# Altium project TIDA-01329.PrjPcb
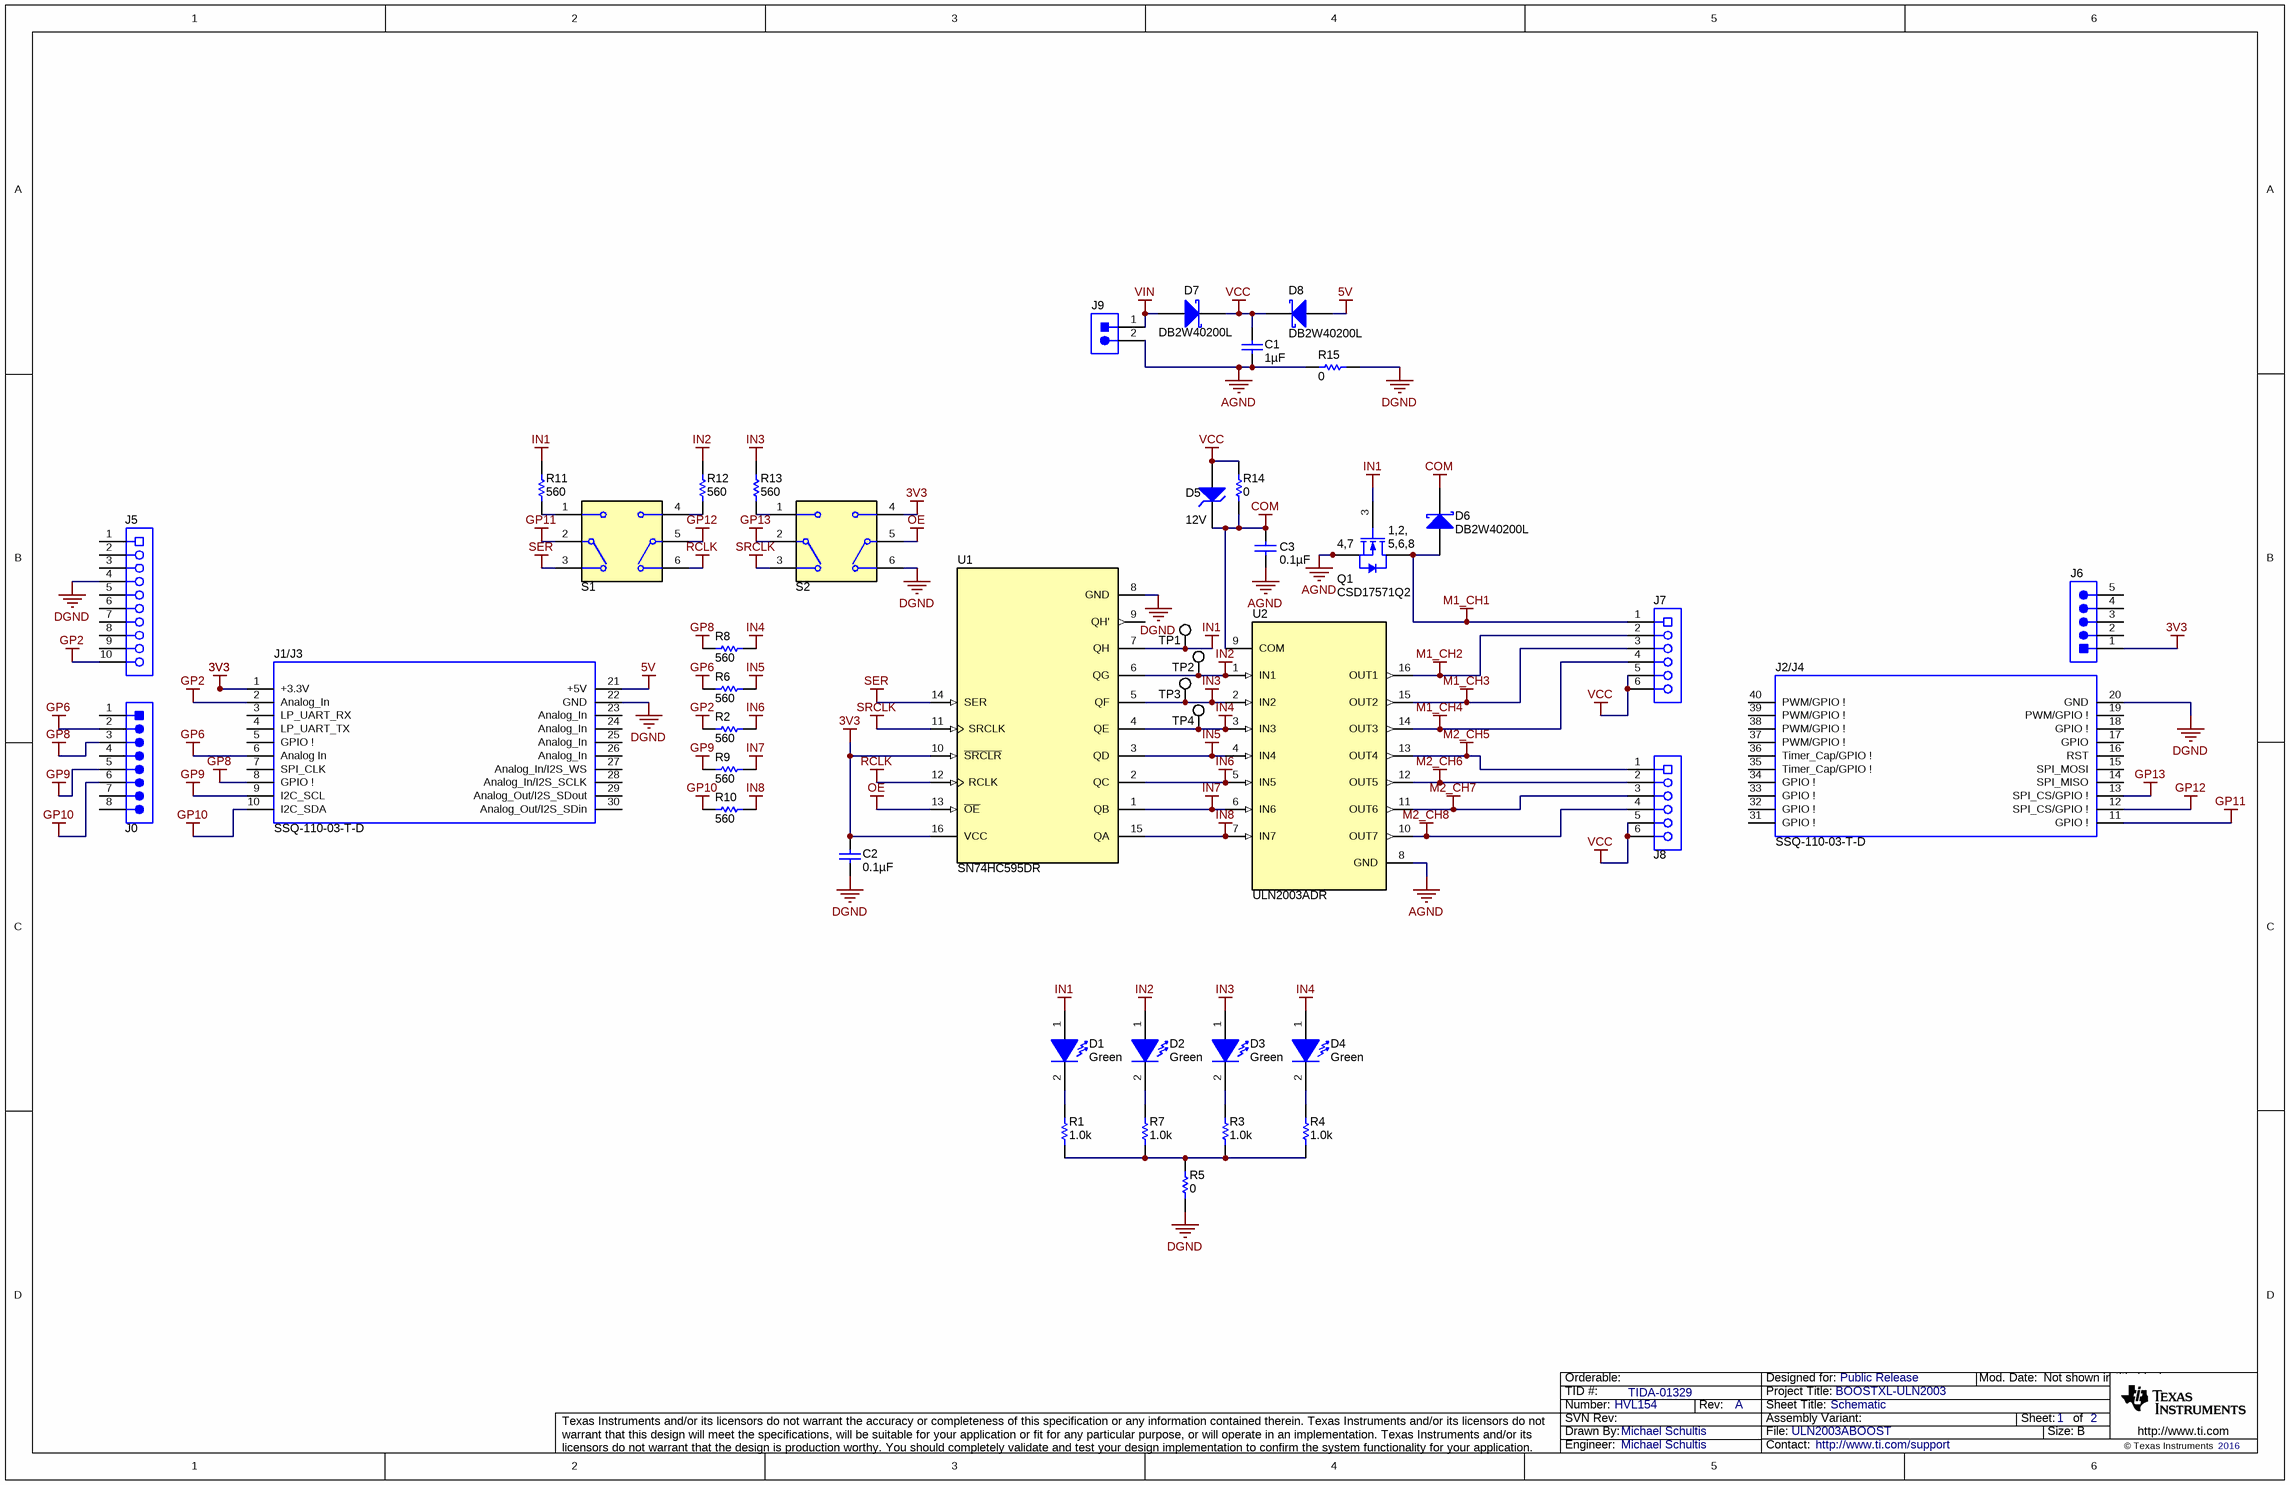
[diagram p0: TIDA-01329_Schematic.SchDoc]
TID: TIDA-01329; TechSupport: http://www.ti.com/support; SCH_Rev: A; PRJ_Title: BOOSTXL-ULN2003; PRJ_Number: HVL154; PRJ_Engineer: Michael Schultis; PRJ_Customer: Public Release; PCB_Rev: A; PCB_Layout: Michael Schultis; CopyrightYear: 2016
2 sheets, 52 parts. Net scope: global (net labels, ports and power ports of the same name join across sheets).
Board file: TIDA-01329.PcbDoc
Sheets:
  TIDA-01329_Schematic.SchDoc
  TIDA-01329_Hardware.SchDoc

## Sheet TIDA-01329_Schematic.SchDoc: Schematic
size 431 x 279 mm; Date: Not shown in title block; ApprovedBy: Not shown in title block; CheckedBy: Not shown in title block; Author: Not shown in title block; CompanyName: Not shown in title block; DrawnBy: Michael Schultis; Engineer: Not shown in title block; Organization: Not shown in title block; Address1: Not shown in title block; Address2: Not shown in title block; Address3: Not shown in title block; Address4: Not shown in title block; DocumentNumber: 1; Revision: Use project parameter SCH_Rev; SheetNumber: 1; SheetTotal: 2; PageSetup: Record=PageOptions¦CenterHorizontal=True¦CenterVertical=True¦PrintScale=1.00¦XCorrection=1.00¦YCorrection=1.00¦PrintKind=0¦BorderSize=5000000¦LeftOffset=0¦BottomOffset=0¦Orientation=2¦PaperLength=1000¦PaperWidth=1000¦Scale=100¦PaperSource=15¦PrintQuality=600¦MediaType=1¦DitherType=10¦PaperKind=Letter¦PrintScaleMode=1

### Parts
C1  ValueDisplayed: 1µF  [0805_HV]  (hidden comment: GRM21BR71H105KA12L)
C2  ValueDisplayed: 0.1µF  [0603]  (hidden comment: GRM188R71H104KA93D)
C3  ValueDisplayed: 0.1µF  [0603]  (hidden comment: GRM188R71H104KA93D)
D1  value Green  [LG L29K_GREEN]  (hidden comment: LG L29K-G2J1-24-Z)
D2  value Green  [LG L29K_GREEN]  (hidden comment: LG L29K-G2J1-24-Z)
D3  value Green  [LG L29K_GREEN]  (hidden comment: LG L29K-G2J1-24-Z)
D4  value Green  [LG L29K_GREEN]  (hidden comment: LG L29K-G2J1-24-Z)
D5  value 12V  [powerDI123]  (hidden comment: DFLZ12-7)
D6  DB2W40200L  [SOD-123F]
D7  DB2W40200L  [SOD-123F]
D8  DB2W40200L  [SOD-123F]
J0  TSW-108-07-G-S  [TSW-108-07-G-S]  (value not drawn)
J1/J3  SSQ-110-03-T-D  [BoosterPack_40pin_J1J3]
J2/J4  SSQ-110-03-T-D  [BoosterPack_40pin_J2J4]
J5  SSQ-110-03-F-S  [Samtec_SSQ-110-03-x-S]  (value not drawn)
J6  TSW-105-07-G-S  [TSW-105-07-G-S]  (value not drawn)
J7  PPPC061LGBN-RC  [Sullins_xPxC061LGBN]  (value not drawn)
J8  PPPC061LGBN-RC  [Sullins_xPxC061LGBN]  (value not drawn)
J9  PEC02SAAN  [CONN_PEC02SAAN]  (value not drawn)
Q1  CSD17571Q2  [TRANS_NexFET_Q2]
R1  ValueDisplayed: 1.0k  [0402]  (hidden comment: CRCW04021K00JNED)
R2  ValueDisplayed: 560  [0402]  (hidden comment: CRCW0402560RJNED)
R3  ValueDisplayed: 1.0k  [0402]  (hidden comment: CRCW04021K00JNED)
R4  ValueDisplayed: 1.0k  [0402]  (hidden comment: CRCW04021K00JNED)
R5  ValueDisplayed: 0  [0603]  (hidden comment: ERJ-3GEY0R00V)
R6  ValueDisplayed: 560  [0402]  (hidden comment: CRCW0402560RJNED)
R7  ValueDisplayed: 1.0k  [0402]  (hidden comment: CRCW04021K00JNED)
R8  ValueDisplayed: 560  [0402]  (hidden comment: CRCW0402560RJNED)
R9  ValueDisplayed: 560  [0402]  (hidden comment: CRCW0402560RJNED)
R10  ValueDisplayed: 560  [0402]  (hidden comment: CRCW0402560RJNED)
R11  ValueDisplayed: 560  [0402]  (hidden comment: CRCW0402560RJNED)
R12  ValueDisplayed: 560  [0402]  (hidden comment: CRCW0402560RJNED)
R13  ValueDisplayed: 560  [0402]  (hidden comment: CRCW0402560RJNED)
R14  ValueDisplayed: 0  [0603]  (hidden comment: ERJ-3GEY0R00V)
R15  ValueDisplayed: 0  [1206]  (hidden comment: ERJ-8GEY0R00V)
S1  CAS-D20TA  [SW_CAS-D20TA]  (value not drawn)
S2  CAS-D20TA  [SW_CAS-D20TA]  (value not drawn)
TP1  5015  [Testpoint_Keystone_Miniature]  (value not drawn)
TP2  5015  [Testpoint_Keystone_Miniature]  (value not drawn)
TP3  5015  [Testpoint_Keystone_Miniature]  (value not drawn)
TP4  5015  [Testpoint_Keystone_Miniature]  (value not drawn)
U1  SN74HC595DR  [D0016A_N]
U2  ULN2003ADR  [D0016A_N]

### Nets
3V3: C2.1 J1/J3.1(+3.3V) J6.1 S2.4 U1.10(~{SRCLR}) U1.16(VCC)
5V: D8.2(A) J1/J3.21(+5V)
AGND: C1.2 C3.2 J9.2 Q1.4(S) Q1.7(S) R15.1 U2.8(GND)
COM: C3.1 D5.1(K) D6.1(K) R14.1 U2.9(COM)
DGND: C2.2 J1/J3.22(GND) J2/J4.20(GND) J5.4 R5.1 R15.2 S2.6 U1.8(GND)
GP2: J1/J3.2(Analog_In) J5.10 R2.2
GP6: J0.2 J1/J3.6(Analog_In) R6.2
GP8: J0.3 J1/J3.8(GPIO_!) R8.2
GP9: J0.5 J1/J3.9(I2C_SCL) R9.2
GP10: J0.6 J1/J3.10(I2C_SDA) R10.2
GP11: J2/J4.11(GPIO_!) S1.2(C)
GP12: J2/J4.12(SPI_CS/GPIO_!) S1.5(C)
GP13: J2/J4.13(SPI_CS/GPIO_!) S2.2(C)
IN1: D1.1(A) Q1.3(G) R11.2 TP1.1 U1.7(QH)
IN2: D2.1(A) R12.2 TP2.1 U1.6(QG) U2.1(IN1)
IN3: D3.1(A) R13.2 TP3.1 U1.5(QF) U2.2(IN2)
IN4: D4.1(A) R8.1 TP4.1 U1.4(QE) U2.3(IN3)
IN5: R6.1 U1.3(QD) U2.4(IN4)
IN6: R2.1 U1.2(QC) U2.5(IN5)
IN7: R9.1 U1.1(QB) U2.6(IN6)
IN8: R10.1 U1.15(QA) U2.7(IN7)
M1_CH1: D6.2(A) J7.1 Q1.1(D) Q1.2(D) Q1.5(D) Q1.6(D) Q1.8(D)
M1_CH2: J7.2 U2.16(OUT1)
M1_CH3: J7.3 U2.15(OUT2)
M1_CH4: J7.4 U2.14(OUT3)
M2_CH5: J8.1 U2.13(OUT4)
M2_CH6: J8.2 U2.12(OUT5)
M2_CH7: J8.3 U2.11(OUT6)
M2_CH8: J8.4 U2.10(OUT7)
OE: S2.5(C) U1.13(~{OE})
RCLK: S1.6 U1.12(RCLK)
SER: S1.3 U1.14(SER)
SRCLK: S2.3 U1.11(SRCLK)
VCC: C1.1 D5.2(A) D7.1(K) D8.1(K) J7.5 J7.6 J8.5 J8.6 R14.2
VIN: D7.2(A) J9.1
NetD1_2: D1.2(K) R1.2
NetD2_2: D2.2(K) R7.2
NetD3_2: D3.2(K) R3.2
NetD4_2: D4.2(K) R4.2
NetR1_1: R1.1 R3.1 R4.1 R5.2 R7.1
NetR11_1: R11.1 S1.1
NetR12_1: R12.1 S1.4
NetR13_1: R13.1 S2.1

Not connected (* = marked no-connect by the designer): J0 1 4 7 8; J1/J3 3(LP_UART_RX) 4(LP_UART_TX) 5(GPIO_!) 7(SPI_CLK) 23(Analog_In) 24(Analog_In) 25(Analog_In) 26(Analog_In) 27(Analog_In/I2S_WS) 28(Analog_In/I2S_SCLK) 29(Analog_Out/I2S_SDout) 30(Analog_Out/I2S_SDin); J2/J4 14(SPI_MISO) 15(SPI_MOSI) 16(RST) 17(GPIO) 18(GPIO_!) 19(PWM/GPIO_!) 31(GPIO_!) 32(GPIO_!) 33(GPIO_!) 34(GPIO_!) 35(Timer_Cap/GPIO_!) 36(Timer_Cap/GPIO_!) 37(PWM/GPIO_!) 38(PWM/GPIO_!) 39(PWM/GPIO_!) 40(PWM/GPIO_!); J5 1 2 3 5 6 7 8 9; J6 2 3 4 5; U1 9(QH')

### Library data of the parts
C1 = GRM21BR71H105KA12L: CAP, CERM, 1 µF, 50 V, +/- 10%, X7R, 0805; Manufacturer: MuRata; Polarized: N; CompType: Capacitor; Value: 1uF; U/M: EA; Cap_F: 0.000001; Tolerance_%: 10; Value1: Unknown; VDC_V: 50; Value2: 50V; TaMin_C: -55; TaMax_C: 125; Cap_Case: 0805; AEC Category: Q200
C2 C3 = GRM188R71H104KA93D: CAP, CERM, 0.1 µF, 50 V, +/- 10%, X7R, 0603; Manufacturer: MuRata; Polarized: N; CompType: Capacitor; Value: 0.1uF; U/M: EA; Cap_F: 0.0000001; Tolerance_%: 10; Value1: Unknown; VDC_V: 50; Value2: 50V; TaMin_C: -55; TaMax_C: 125; AEC Category: Q200
D1-D4 = LG L29K-G2J1-24-Z: LED, Green, SMD; Manufacturer: OSRAM; Vf_V: 1.7; Value2: 1.7V; Io_A: 0.002; Tjmax_C: 110; Value1: W; U/M: EA
D5 = DFLZ12-7: Diode, Zener, 12 V, 1 W, PowerDI123; Manufacturer: Diodes Inc.; SymbolCreator: a0412235; U/M: EA; Power_W: 1; Vz_V: 12; Value1: 1W; RJA_CperW: 110; AEC Category: Q101
D6-D8 = DB2W40200L: Diode, Schottky, 40 V, 2 A, SOD-123F; Manufacturer: Panasonic; U/M: EA; Vf_V: 0.47; Value: 40V; Value1: 2A; Value2: 0.47V; Io_A: 2; Vr_V: 40; TJmax_C: 150; AEC Category: Q101; AEC Qualified: N
J0 = TSW-108-07-G-S: Header, 100mil, 8x1, Gold, TH; Manufacturer: Samtec; SymbolCreator: a0411947; Pitch_mm: 2.54; Gender: Male; Shrouded: N; Row_Count: 1; Current_A: 6.3; Voltage_V: 550; Cert_CSA: Y
J1/J3 = BoosterPack_40pin_J1J3: Receptacle, 2.54mm, 10x2, Tin, TH; Manufacturer: Samtec; Alternate Manufacturer: Major League Electronics; Alternate PartNumber: CRD-081413-A-G; SymbolCreator: a0412235; Note: Booster Pack 40 pin J1 and J3
J2/J4 = BoosterPack_40pin_J2J4: Receptacle, 2.54mm, 10x2, Tin, TH; Manufacturer: Samtec; Alternate Manufacturer: Major League Electronics; Alternate PartNumber: CRD-081413-A-G; SymbolCreator: a0412235; Note: Booster Pack 40 pin J2 and J4
J5 = SSQ-110-03-F-S: Receptacle, 2.54mm, 10x1, Gold, TH; Manufacturer: Samtec; SymbolCreator: a0411947; Pitch_mm: 2.54; Gender: Female; Row_Count: 1
J6 = TSW-105-07-G-S: Header, 100mil, 5x1, Gold, TH; Manufacturer: Samtec; SymbolCreator: a0412235; Pitch_mm: 2.54; Gender: Male; Shrouded: N; Row_Count: 1; Current_A: 6.3; Voltage_V: 550; Cert_CSA: Y
J7 J8 = PPPC061LGBN-RC: Receptacle, 2.54mm, 6x1, Gold, R/A, Black, TH; Manufacturer: Sullins Connector Solutions; SymbolCreator: a0411947; Pitch_mm: 2.54; Gender: Female; Row_Count: 1; Current_A: 3; Voltage_V: 250; Cert_UL: Y
J9 = PEC02SAAN: Header, 100mil, 2x1, Tin, TH; Manufacturer: Sullins Connector Solutions; SymbolCreator: a0412235; Pitch_mm: 2.54; Gender: Male; Shrouded: N; Row_Count: 1; Current_A: 3; Voltage_V: 1800; Cert_UL: Y
Q1 = CSD17571Q2: MOSFET, N-CH, 30 V, 7.6 A, SON 2x2mm; Manufacturer: Texas Instruments; Alternate Manufacturer: None; U/M: EA; ChType: N; Value: 30V; VdsMax_V: 30; Value1: 0.029 ohm; Rdson45_ohm: 0.029; Value2: 2.4 nC; QgTyp_nC: 2.4; Vgs_V: 20; IdsMax_A: 7.6; AEC Category: Q101
R1 R3 R4 R7 = CRCW04021K00JNED: RES, 1.0 k, 5%, 0.063 W, 0402; Manufacturer: Vishay-Dale; CompType: Resistor; Value: 1.0k; Res_ohm: 1000; Value_Code: 1k00; Tolerance_%: 5; Power_W: 0.063; Value2: 0.063W; VDC_V: 50; TempCo: 200 ppm/C; SizeArea_mm2: 0.5; SizeX_mm: 1; SizeZ_mm: 0.6; EIA_Code: E24; U/M: EA; AEC Category: Q200
R2 R6 R8-R13 = CRCW0402560RJNED: RES, 560, 5%, 0.063 W, 0402; Manufacturer: Vishay-Dale; CompType: Resistor; Value: 560; Value_Code: 560R; Tolerance_%: 5; Power_W: 0.063; Value2: 0.063W; VDC_V: 50; TempCo: 200 ppm/C; SizeArea_mm2: 0.5; SizeX_mm: 1; SizeZ_mm: 0.6; EIA_Code: E24; U/M: EA; AEC Category: Q200
R5 R14 = ERJ-3GEY0R00V: RES, 0, 5%, 0.1 W, 0603; Manufacturer: Panasonic; CompType: Resistor; Value: 0; Value_Code: 0000; Tolerance_%: 5; Power_W: 0.1; Value2: 0.1W; VDC_V: 50; TempCo: 600 ppm/C; EIA_Code: E24; U/M: EA; AEC Category: Q200
R15 = ERJ-8GEY0R00V: RES, 0, 5%, 0.25 W, 1206; Manufacturer: Panasonic; CompType: Resistor; Value: 0; Value_Code: 0000; Tolerance_%: 5; Power_W: 0.25; Value2: 0.25W; VDC_V: 200; TempCo: 600 ppm/C; EIA_Code: E24; U/M: EA; AEC Category: Q200
S1 S2 = CAS-D20TA: Switch, Dual SPDT,  2 Pos, 0.1A, 6VDC, SMD; Manufacturer: Copal Electronics; SymbolCreator: Altium; VDC_V: 6; SwitchFunction: On-On; PositionCount: 2; CurrentRating_mA: 100
TP1-TP4 = 5015: Test Point, Miniature, SMT; Manufacturer: Keystone; CompType: Test Point Loop
U1 = SN74HC595DR: 8-Bit Shift Registers With 3-State Output Register, D0016A; Manufacturer: Texas Instruments; SymbolCreator: Altium; CompType: IC; U/M: EA
U2 = ULN2003ADR: 7-Channel Relay and Inductive Load Sink Driver, D0016A; Manufacturer: Texas Instruments; SymbolCreator: a0411947; CompType: IC; U/M: EA

## Sheet TIDA-01329_Hardware.SchDoc: Hardware
size 431 x 279 mm; Date: Not shown in title block; ApprovedBy: Not shown in title block; CheckedBy: Not shown in title block; Author: Not shown in title block; CompanyName: Not shown in title block; Engineer: Not shown in title block; Organization: Not shown in title block; Address1: Not shown in title block; Address2: Not shown in title block; Address3: Not shown in title block; Address4: Not shown in title block; DocumentNumber: 2; Revision: Use project parameter SCH_Rev; SheetNumber: 2; SheetTotal: 2; PageSetup: Record=PageOptions¦CenterHorizontal=True¦CenterVertical=True¦PrintScale=1.00¦XCorrection=1.00¦YCorrection=1.00¦PrintKind=0¦BorderSize=5000000¦LeftOffset=0¦BottomOffset=0¦Orientation=2¦PaperLength=1000¦PaperWidth=1000¦Scale=100¦PaperSource=15¦PrintQuality=600¦MediaType=1¦DitherType=10¦PaperKind=Letter¦PrintScaleMode=1
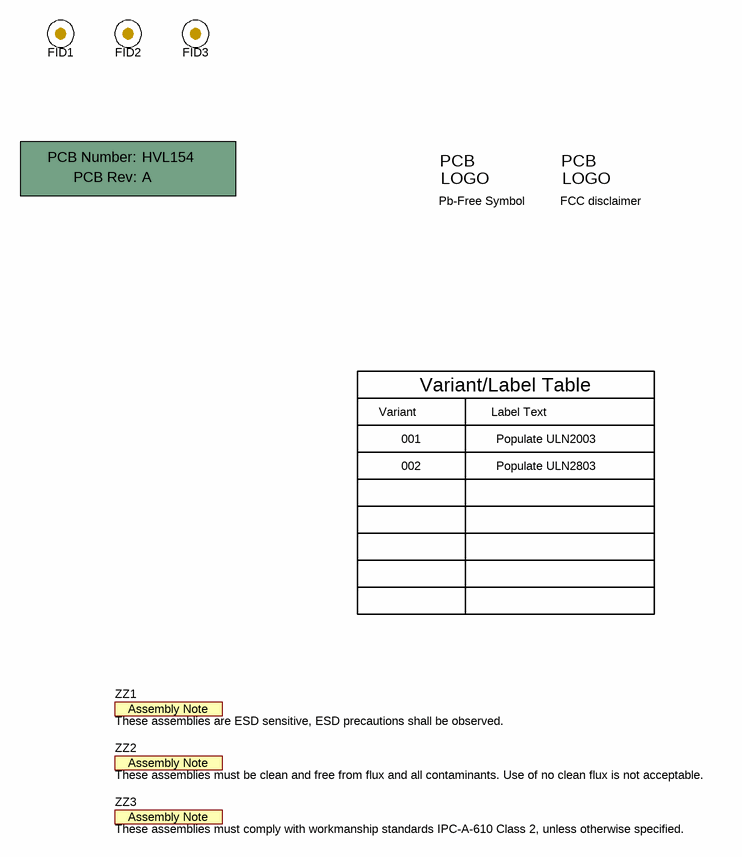
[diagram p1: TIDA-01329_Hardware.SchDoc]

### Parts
!PCB  Printed Circuit Board  (value not drawn)  (mechanical)
FID1  Fiducial  [Fiducial10-20]  (value not drawn)
FID2  Fiducial  [Fiducial10-20]  (value not drawn)
FID3  Fiducial  [Fiducial10-20]  (value not drawn)
Logo2  Pb-Free Symbol  [Pb-Free_Overlay_Small]  (no BOM)
Logo3  FCC disclaimer  [FCC_disclaimer]  (no BOM)
ZZ1  These assemblies are ESD sensitive, ESD precautions shall be observed.  [AssemblyNote]  (no BOM)
ZZ2  These assemblies must be clean and free from flux and all contaminants. Use of no clean flux is not acceptable.  [AssemblyNote]  (no BOM)
ZZ3  These assemblies must comply with workmanship standards IPC-A-610 Class 2, unless otherwise specified.  [AssemblyNote]  (no BOM)

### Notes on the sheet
- Variant
- Variant/Label Table
- Label Text
- 001
- 002
- Populate ULN2003
- Populate ULN2803

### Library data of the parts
!PCB = PCB: Manufacturer: Any; PartNumber: HVL154; SymbolCreator: a0412235
FID1-FID3 = Fiducial: Fiducial mark.  There is nothing to buy or mount.; SymbolCreator: codlsc
Logo2 = Pb-Free: SymbolCreator: a0412235
Logo3 = FCC_disclaimer: SymbolCreator: codlsc
ZZ1-ZZ3 = AssemblyNote: SymbolCreator: codlsc

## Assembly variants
001: not fitted J0 J5 J6 J9 R2 R6 R9 R10 U3
002: not fitted J0 J5 J6 J9 U2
